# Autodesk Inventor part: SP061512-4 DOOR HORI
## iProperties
Created: 2012-06
Part Number: SP061512-4 DOOR HORI
Material: Aluminum-6061
Description: CLAMP PROFILE 45X32
Document SubType Name: Modeling
Designer: Administrator
Stock Number: 20.1053 CLAMP PROFILE 45X32
Density: 2.71 g/cm^3
Mass: 1962.54 g
Surface Area: 4381.76 cm^2
Volume: 724.185 cm^3
FINISH: CLEAR ANODIZED
Author: Administrator
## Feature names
1. Extrusion1
